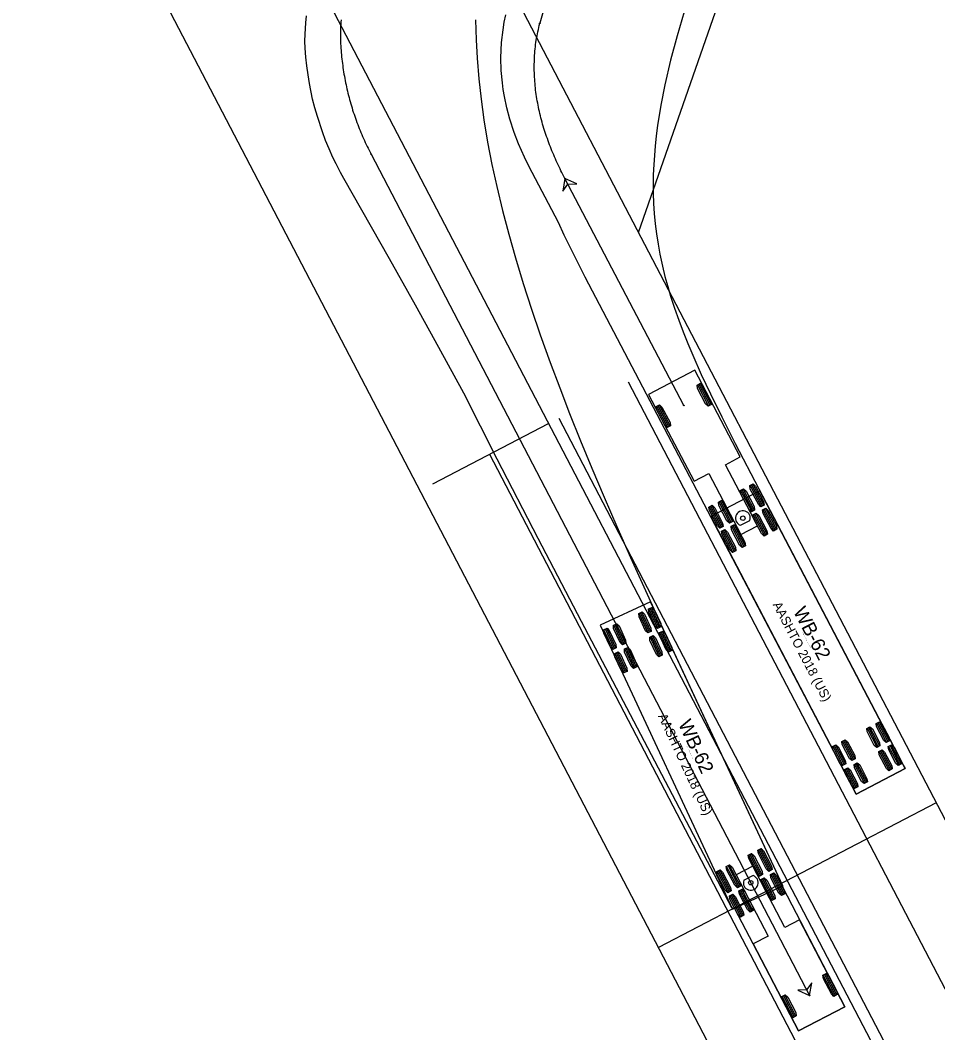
# Model space of a CAD drawing. Extents: x 2297881 to 2300600, y 559917 to 564426.
# Drawn here: x 2298929.2 to 2299069.8, y 562494.5 to 562649.6 of the extents above; entities that cross this region are included whole.
import ezdxf

# ---------------------------------------------------------------- set-up
doc = ezdxf.new("R2010")
doc.units = 0
for name, color, linetype in [('DR_X_Elev_Flow', 7, 'Continuous'), ('GE_X_Alignment', 7, 'Continuous'), ('PM_P_Channelizing_Line', 7, 'Continuous'), ('PM_P_Lane_Line', 7, 'Continuous'), ('SC_Scratch1', 7, 'Continuous'), ('SV_X_Control_Cells_Found', 7, 'Continuous'), ('UT_X_Telecom_Cells', 7, 'Continuous'), ('VG_X_Cells', 7, 'Continuous')]:
    doc.layers.add(name, color=color, linetype=linetype)

msp = doc.modelspace()

# ---------------------------------------------------------------- linework, layer by layer
at = {"layer": 'DR_X_Elev_Flow'}
for p, q in [((2299030.92, 562590.62), (2299012.69, 562625.4)), ((2299030.92, 562590.62), (2299012.69, 562625.4)), ((2299032.6, 562596.02), (2299025.52, 562592.3)), ((2299039.57, 562582.73), (2299032.6, 562596.02)), ((2299033.41, 562593.99), (2299035.11, 562590.74)), ((2299033, 562593.78), (2299034.7, 562590.53)), ((2299033.2, 562593.88), (2299034.91, 562590.64)), ((2299025.52, 562592.3), (2299032.48, 562579.02)), ((2299025.52, 562592.3), (2299025.52, 562592.3)), ((2299026.73, 562590.49), (2299028.43, 562587.24)), ((2299026.93, 562590.6), (2299028.63, 562587.35)), ((2299027.13, 562590.7), (2299028.83, 562587.45)), ((2299037.29, 562581.54), (2299039.57, 562582.73)), ((2299042.21, 562572.15), (2299037.29, 562581.54)), ((2299032.48, 562579.02), (2299034.75, 562580.21)), ((2299034.75, 562580.21), (2299039.67, 562570.82)), ((2299041.28, 562578.47), (2299042.98, 562575.22)), ((2299041.48, 562578.58), (2299043.18, 562575.33)), ((2299042.57, 562577.53), (2299035.04, 562573.59)), ((2299039.61, 562577.6), (2299041.32, 562574.35)), ((2299039.82, 562577.71), (2299041.52, 562574.46)), ((2299040.02, 562577.81), (2299041.72, 562574.56)), ((2299041.08, 562578.36), (2299042.78, 562575.12)), ((2299064.85, 562535.01), (2299042.57, 562577.53)), ((2299036.26, 562575.84), (2299037.97, 562572.6)), ((2299036.47, 562575.95), (2299038.17, 562572.7)), ((2299036.67, 562576.06), (2299038.37, 562572.81)), ((2299034.8, 562575.08), (2299036.5, 562571.83)), ((2299035.01, 562575.18), (2299036.71, 562571.94)), ((2299035.21, 562575.29), (2299036.91, 562572.04)), ((2299041.56, 562573.88), (2299043.27, 562570.63)), ((2299041.77, 562573.98), (2299043.47, 562570.74)), ((2299041.97, 562574.09), (2299043.67, 562570.84)), ((2299043.03, 562574.64), (2299044.73, 562571.4)), ((2299043.23, 562574.75), (2299044.93, 562571.5)), ((2299043.43, 562574.86), (2299045.13, 562571.61)), ((2299035.04, 562573.59), (2299057.32, 562531.07)), ((2299035.04, 562573.59), (2299035.04, 562573.59)), ((2299038.42, 562572.23), (2299040.12, 562568.98)), ((2299038.62, 562572.34), (2299040.32, 562569.09)), ((2299039.63, 562572.25), (2299041.06, 562573)), ((2299036.75, 562571.36), (2299038.45, 562568.11)), ((2299036.95, 562571.46), (2299038.66, 562568.22)), ((2299037.16, 562571.57), (2299038.86, 562568.32)), ((2299038.21, 562572.12), (2299039.91, 562568.87)), ((2299039.67, 562570.82), (2299042.21, 562572.15)), ((2299059.2, 562541.25), (2299060.73, 562538.33)), ((2299059.4, 562541.36), (2299060.93, 562538.44)), ((2299060.46, 562541.91), (2299061.99, 562538.99)), ((2299060.66, 562542.02), (2299062.19, 562539.1)), ((2299060.86, 562542.13), (2299062.39, 562539.2)), ((2299059, 562541.15), (2299060.53, 562538.22)), ((2299053.74, 562538.39), (2299055.27, 562535.47)), ((2299053.94, 562538.5), (2299055.47, 562535.58)), ((2299054.15, 562538.61), (2299055.68, 562535.68)), ((2299055.2, 562539.16), (2299056.73, 562536.24)), ((2299055.4, 562539.27), (2299056.94, 562536.34)), ((2299055.61, 562539.37), (2299057.14, 562536.45)), ((2299062.31, 562538.37), (2299063.85, 562535.45)), ((2299062.52, 562538.48), (2299064.05, 562535.55)), ((2299062.72, 562538.58), (2299064.25, 562535.66)), ((2299060.85, 562537.6), (2299062.38, 562534.68)), ((2299061.06, 562537.71), (2299062.59, 562534.79)), ((2299061.26, 562537.82), (2299062.79, 562534.89)), ((2299056, 562535.06), (2299057.53, 562532.14)), ((2299057.06, 562535.62), (2299058.59, 562532.69)), ((2299057.26, 562535.72), (2299058.79, 562532.8)), ((2299057.32, 562531.07), (2299064.85, 562535.01)), ((2299057.46, 562535.83), (2299059, 562532.91)), ((2299055.6, 562534.85), (2299057.13, 562531.93)), ((2299055.8, 562534.96), (2299057.33, 562532.03))]:
    msp.add_line(p, q, dxfattribs=at)
for points in [[(2299056.66, 562532.32), (2299015.81, 562610.29), (2299013.54, 562614.77), (2299012.6, 562616.71), (2299011.71, 562618.67), (2299007.18, 562627.3), (2299006.51, 562628.65), (2299005.59, 562630.7), (2299004.93, 562632.43), (2299004.25, 562634.5), (2299003.79, 562636.24), (2299003.42, 562637.98), (2299003.25, 562639.03), (2299003.11, 562640.08), (2299002.94, 562641.95), (2299002.89, 562643.9), (2299002.91, 562645.07), (2299002.98, 562646.24), (2299003.21, 562648.18), (2299003.4, 562649.34), (2299003.65, 562650.49)], [(2299030.96, 562650.95), (2299029.89, 562647.27), (2299028.9, 562643.54), (2299028.01, 562639.73), (2299027.4, 562636.62), (2299026.9, 562633.5), (2299026.69, 562631.94), (2299026.52, 562630.37), (2299026.31, 562627.54), (2299026.24, 562625.97), (2299026.22, 562624.72), (2299026.23, 562623.15), (2299026.29, 562621.58), (2299026.39, 562620.02), (2299026.54, 562618.46), (2299026.73, 562616.9), (2299026.97, 562615.34), (2299027.26, 562613.79), (2299027.66, 562611.94), (2299028.03, 562610.4), (2299028.45, 562608.87), (2299028.9, 562607.34), (2299029.49, 562605.52), (2299030.13, 562603.7), (2299030.81, 562601.89), (2299031.53, 562600.09), (2299032.28, 562598.3), (2299033.6, 562595.34), (2299034.99, 562592.39), (2299036.72, 562588.88), (2299038.79, 562584.8), (2299042.41, 562577.84), (2299064.25, 562536.16), (2299064.55, 562535.49), (2299064.85, 562535.01), (2299057.32, 562531.07), (2299056.66, 562532.32)], [(2299012.69, 562625.4), (2299012.54, 562625.7), (2299012.38, 562626), (2299012.23, 562626.29), (2299012.08, 562626.59), (2299011.94, 562626.89), (2299011.79, 562627.19), (2299011.65, 562627.49), (2299011.51, 562627.79), (2299011.37, 562628.1), (2299011.23, 562628.4), (2299011.1, 562628.71), (2299010.97, 562629.01), (2299010.84, 562629.32), (2299010.71, 562629.63), (2299010.58, 562629.94), (2299010.46, 562630.25), (2299010.34, 562630.56), (2299010.22, 562630.87), (2299010.11, 562631.18), (2299010, 562631.5), (2299009.89, 562631.81), (2299009.78, 562632.13), (2299009.67, 562632.44), (2299009.57, 562632.76), (2299009.47, 562633.08), (2299009.38, 562633.4), (2299009.28, 562633.72), (2299009.19, 562634.04), (2299009.11, 562634.36), (2299009.02, 562634.68), (2299008.94, 562635.01), (2299008.86, 562635.33), (2299008.79, 562635.65), (2299008.71, 562635.98), (2299008.65, 562636.31), (2299008.58, 562636.63), (2299008.52, 562636.96), (2299008.46, 562637.29), (2299008.4, 562637.62), (2299008.35, 562637.95), (2299008.3, 562638.28), (2299008.26, 562638.61), (2299008.21, 562638.94), (2299008.18, 562639.27), (2299008.14, 562639.6), (2299008.11, 562639.93), (2299008.08, 562640.26), (2299008.06, 562640.6), (2299008.04, 562640.93), (2299008.02, 562641.26), (2299008.01, 562641.59), (2299008, 562641.93), (2299008, 562642.26), (2299008, 562642.59), (2299008, 562642.93), (2299008.01, 562643.26), (2299008.02, 562643.59), (2299008.03, 562643.93), (2299008.05, 562644.26), (2299008.08, 562644.59), (2299008.1, 562644.92), (2299008.14, 562645.26), (2299008.17, 562645.59), (2299008.21, 562645.92), (2299008.26, 562646.25), (2299008.31, 562646.58), (2299008.36, 562646.91), (2299008.42, 562647.24), (2299008.48, 562647.56), (2299008.54, 562647.89), (2299008.62, 562648.22), (2299008.69, 562648.54), (2299008.77, 562648.86), (2299008.85, 562649.19)], [(2299012.69, 562625.4), (2299012.35, 562623.43), (2299013.16, 562624.52), (2299014.51, 562624.56), (2299012.69, 562625.4)], [(2299012.69, 562625.4), (2299012.35, 562623.43), (2299013.16, 562624.52), (2299014.51, 562624.56), (2299012.69, 562625.4)]]:
    msp.add_lwpolyline(points, dxfattribs=at)
for points in [[(2299012.69, 562625.4), (2299012.35, 562623.43), (2299013.16, 562624.52), (2299014.51, 562624.56)], [(2299012.69, 562625.4), (2299012.35, 562623.43), (2299013.16, 562624.52), (2299014.51, 562624.56)], [(2299032.95, 562593.75), (2299033.46, 562594.02), (2299033.85, 562593.64), (2299035.07, 562591.3), (2299035.16, 562590.77), (2299034.65, 562590.5), (2299034.26, 562590.88), (2299033.04, 562593.22)], [(2299026.68, 562590.46), (2299027.18, 562590.73), (2299027.57, 562590.35), (2299028.8, 562588.02), (2299028.88, 562587.48), (2299028.38, 562587.22), (2299027.99, 562587.59), (2299026.76, 562589.93)], [(2299041.03, 562578.34), (2299041.53, 562578.6), (2299041.92, 562578.23), (2299043.15, 562575.89), (2299043.23, 562575.36), (2299042.73, 562575.09), (2299042.34, 562575.47), (2299041.11, 562577.8)], [(2299039.56, 562577.57), (2299040.07, 562577.84), (2299040.46, 562577.46), (2299041.69, 562575.12), (2299041.77, 562574.59), (2299041.27, 562574.32), (2299040.88, 562574.7), (2299039.65, 562577.04)], [(2299034.75, 562575.05), (2299035.26, 562575.32), (2299035.65, 562574.94), (2299036.87, 562572.6), (2299036.96, 562572.07), (2299036.45, 562571.8), (2299036.06, 562572.18), (2299034.84, 562574.52)], [(2299036.21, 562575.82), (2299036.72, 562576.08), (2299037.11, 562575.71), (2299038.34, 562573.37), (2299038.42, 562572.83), (2299037.92, 562572.57), (2299037.52, 562572.94), (2299036.3, 562575.28)], [(2299041.51, 562573.85), (2299042.02, 562574.12), (2299042.41, 562573.74), (2299043.64, 562571.4), (2299043.72, 562570.87), (2299043.22, 562570.6), (2299042.82, 562570.98), (2299041.6, 562573.32)], [(2299042.98, 562574.62), (2299043.48, 562574.88), (2299043.87, 562574.51), (2299045.1, 562572.17), (2299045.18, 562571.64), (2299044.68, 562571.37), (2299044.29, 562571.74), (2299043.06, 562574.08)], [(2299038.16, 562572.1), (2299038.67, 562572.36), (2299039.06, 562571.99), (2299040.29, 562569.65), (2299040.37, 562569.11), (2299039.86, 562568.85), (2299039.47, 562569.22), (2299038.25, 562571.56)], [(2299036.7, 562571.33), (2299037.21, 562571.6), (2299037.6, 562571.22), (2299038.82, 562568.88), (2299038.91, 562568.35), (2299038.4, 562568.08), (2299038.01, 562568.46), (2299036.79, 562570.8)], [(2299058.95, 562541.12), (2299059.45, 562541.39), (2299059.82, 562541.06), (2299060.92, 562538.95), (2299060.98, 562538.46), (2299060.48, 562538.2), (2299060.11, 562538.53), (2299059.01, 562540.63)], [(2299060.41, 562541.89), (2299060.91, 562542.15), (2299061.28, 562541.82), (2299062.38, 562539.72), (2299062.45, 562539.23), (2299061.94, 562538.96), (2299061.57, 562539.29), (2299060.47, 562541.4)], [(2299053.69, 562538.37), (2299054.2, 562538.63), (2299054.56, 562538.3), (2299055.67, 562536.2), (2299055.73, 562535.71), (2299055.22, 562535.44), (2299054.85, 562535.77), (2299053.75, 562537.88)], [(2299055.15, 562539.13), (2299055.66, 562539.4), (2299056.02, 562539.07), (2299057.13, 562536.96), (2299057.19, 562536.47), (2299056.68, 562536.21), (2299056.32, 562536.54), (2299055.21, 562538.64)], [(2299062.26, 562538.34), (2299062.77, 562538.61), (2299063.14, 562538.28), (2299064.24, 562536.17), (2299064.3, 562535.69), (2299063.79, 562535.42), (2299063.43, 562535.75), (2299062.33, 562537.85)], [(2299060.8, 562537.58), (2299061.31, 562537.84), (2299061.68, 562537.51), (2299062.78, 562535.41), (2299062.84, 562534.92), (2299062.33, 562534.65), (2299061.97, 562534.98), (2299060.86, 562537.09)], [(2299055.55, 562534.82), (2299056.05, 562535.09), (2299056.42, 562534.76), (2299057.52, 562532.66), (2299057.58, 562532.17), (2299057.08, 562531.9), (2299056.71, 562532.23), (2299055.61, 562534.33)], [(2299057.01, 562535.59), (2299057.51, 562535.85), (2299057.88, 562535.53), (2299058.98, 562533.42), (2299059.05, 562532.93), (2299058.54, 562532.67), (2299058.17, 562533), (2299057.07, 562535.1)]]:
    msp.add_lwpolyline(points, close=True, dxfattribs=at)
for centre, radius in [((2299008.85, 562649.19), 0.0417), ((2299008.85, 562649.19), 0.0417), ((2299012.69, 562625.4), 0.0417), ((2299012.69, 562625.4), 0.0417), ((2299012.69, 562625.4), 0.0417), ((2299030.92, 562590.62), 0.0417), ((2299030.92, 562590.62), 0.0417), ((2299039.97, 562573.34), 0.34)]:
    msp.add_circle(centre, radius, dxfattribs=at)
for centre, radius, start, end in [((2299051.52, 562637.89), 44.14, 134.6492, 165.1685), ((2299039.97, 562573.34), 1.14, 342.6515, 252.6515)]:
    msp.add_arc(centre, radius, start, end, dxfattribs=at)
at = {"layer": 'GE_X_Alignment'}
msp.add_line((2298386.28, 563783.36), (2299396.64, 561847.4), dxfattribs=at)
at = {"layer": 'PM_P_Channelizing_Line'}
for p, q in [((2298982.98, 562629.13), (2299050.19, 562500.19)), ((2299025.82, 562560.52), (2299018.11, 562556.93)), ((2299046.09, 562517.01), (2299025.82, 562560.52)), ((2299025.45, 562555.77), (2299024.06, 562558.76)), ((2299025.66, 562555.87), (2299024.27, 562558.86)), ((2299025.87, 562555.97), (2299024.47, 562558.96)), ((2299026.95, 562556.47), (2299025.55, 562559.46)), ((2299027.16, 562556.57), (2299025.76, 562559.56)), ((2299027.36, 562556.66), (2299025.97, 562559.65)), ((2299018.11, 562556.93), (2299038.39, 562513.42)), ((2299021.57, 562553.96), (2299020.18, 562556.95)), ((2299021.78, 562554.06), (2299020.38, 562557.05)), ((2299021.98, 562554.16), (2299020.59, 562557.15)), ((2299020.07, 562553.27), (2299018.68, 562556.26)), ((2299020.28, 562553.36), (2299018.89, 562556.35)), ((2299020.49, 562553.46), (2299019.1, 562556.45)), ((2299027.14, 562552.15), (2299025.75, 562555.14)), ((2299027.35, 562552.24), (2299025.96, 562555.23)), ((2299027.56, 562552.34), (2299026.16, 562555.33)), ((2299028.64, 562552.84), (2299027.24, 562555.83)), ((2299028.84, 562552.94), (2299027.45, 562555.93)), ((2299029.05, 562553.04), (2299027.66, 562556.03)), ((2299021.76, 562549.64), (2299020.37, 562552.63)), ((2299021.97, 562549.74), (2299020.58, 562552.73)), ((2299022.18, 562549.83), (2299020.78, 562552.83)), ((2299023.26, 562550.34), (2299021.86, 562553.33)), ((2299023.47, 562550.43), (2299022.07, 562553.43)), ((2299023.67, 562550.53), (2299022.28, 562553.52)), ((2299044.2, 562519.36), (2299042.51, 562522.61)), ((2299044.4, 562519.46), (2299042.71, 562522.71)), ((2299042.53, 562518.49), (2299040.84, 562521.74)), ((2299042.74, 562518.59), (2299041.04, 562521.85)), ((2299042.94, 562518.7), (2299041.25, 562521.95)), ((2299044, 562519.25), (2299042.3, 562522.5)), ((2299039.18, 562516.74), (2299037.48, 562519.99)), ((2299039.38, 562516.85), (2299037.69, 562520.1)), ((2299039.58, 562516.95), (2299037.89, 562520.2)), ((2299041.48, 562520.01), (2299038.94, 562518.68)), ((2299046.38, 562510.61), (2299041.48, 562520.01)), ((2299037.71, 562515.98), (2299036.02, 562519.23)), ((2299037.92, 562516.08), (2299036.22, 562519.34)), ((2299038.12, 562516.19), (2299036.43, 562519.44)), ((2299038.94, 562518.68), (2299043.84, 562509.28)), ((2299041.53, 562518.57), (2299040.09, 562517.83)), ((2299044.47, 562514.76), (2299042.78, 562518.01)), ((2299044.68, 562514.87), (2299042.98, 562518.12)), ((2299044.88, 562514.97), (2299043.19, 562518.23)), ((2299045.94, 562515.52), (2299044.24, 562518.78)), ((2299046.14, 562515.63), (2299044.45, 562518.88)), ((2299046.34, 562515.74), (2299044.65, 562518.99)), ((2299038.39, 562513.42), (2299046.09, 562517.01)), ((2299041.32, 562513.12), (2299039.63, 562516.37)), ((2299041.52, 562513.23), (2299039.83, 562516.48)), ((2299046.09, 562517.01), (2299046.09, 562517.01)), ((2299039.65, 562512.25), (2299037.96, 562515.5)), ((2299039.86, 562512.36), (2299038.16, 562515.61)), ((2299040.06, 562512.46), (2299038.37, 562515.72)), ((2299041.12, 562513.01), (2299039.42, 562516.27)), ((2299048.66, 562511.79), (2299046.38, 562510.61)), ((2299055.59, 562498.49), (2299048.66, 562511.79)), ((2299043.84, 562509.28), (2299041.56, 562508.1)), ((2299041.56, 562508.1), (2299048.49, 562494.79)), ((2299053.97, 562500.09), (2299052.28, 562503.34)), ((2299054.18, 562500.2), (2299052.48, 562503.45)), ((2299054.38, 562500.3), (2299052.69, 562503.56)), ((2299047.69, 562496.82), (2299046, 562500.07)), ((2299047.9, 562496.93), (2299046.2, 562500.18)), ((2299048.1, 562497.03), (2299046.4, 562500.28)), ((2299048.49, 562494.79), (2299055.59, 562498.49)), ((2299055.59, 562498.49), (2299055.59, 562498.49))]:
    msp.add_line(p, q, dxfattribs=at)
for points in [[(2298999.01, 562649.7), (2298999.08, 562646.64), (2298999.22, 562643.84), (2298999.49, 562640.68), (2298999.84, 562637.53), (2299000.28, 562634.39), (2299000.85, 562630.96), (2299001.51, 562627.56), (2299002.24, 562624.18), (2299003.12, 562620.51), (2299004.08, 562616.86), (2299005.12, 562613.22), (2299006.31, 562609.28), (2299007.58, 562605.35), (2299008.92, 562601.43), (2299010.43, 562597.22), (2299011.89, 562593.31), (2299013.4, 562589.41), (2299015.07, 562585.21), (2299016.8, 562581.02), (2299018.7, 562576.54), (2299020.64, 562572.07), (2299022.75, 562567.3), (2299025.04, 562562.25), (2299027.36, 562557.2), (2299046.06, 562517.08), (2299046.08, 562516.73), (2299055.59, 562498.49), (2299048.49, 562494.79), (2299041.55, 562508.11), (2299038.74, 562513.5), (2299038.26, 562513.66), (2299015.24, 562557.52), (2299008.6, 562570.22), (2299002.31, 562582.38), (2298997.21, 562592.48), (2298993.38, 562599.52), (2298989.8, 562605.98), (2298985.8, 562613.1), (2298978.8, 562625.38), (2298978.28, 562626.34), (2298977.61, 562627.64), (2298977.14, 562628.61), (2298976.56, 562629.92), (2298976.02, 562631.23), (2298975.52, 562632.55), (2298974.75, 562634.88), (2298974.37, 562636.22), (2298974.03, 562637.57), (2298973.54, 562639.93), (2298973.32, 562641.29), (2298973.13, 562642.65), (2298972.99, 562644.01), (2298972.88, 562645.39), (2298972.85, 562646.45), (2298972.86, 562647.51), (2298972.97, 562649.26), (2298973.08, 562650.31)], [(2298978.39, 562649.69), (2298978.36, 562649.36), (2298978.33, 562649.03), (2298978.31, 562648.7), (2298978.3, 562648.36), (2298978.29, 562648.03), (2298978.28, 562647.7), (2298978.28, 562647.36), (2298978.28, 562647.03), (2298978.29, 562646.7), (2298978.3, 562646.36), (2298978.32, 562646.03), (2298978.34, 562645.7), (2298978.36, 562645.36), (2298978.38, 562645.03), (2298978.41, 562644.7), (2298978.44, 562644.37), (2298978.47, 562644.04), (2298978.51, 562643.7), (2298978.55, 562643.37), (2298978.59, 562643.04), (2298978.63, 562642.71), (2298978.68, 562642.38), (2298978.73, 562642.05), (2298978.78, 562641.72), (2298978.83, 562641.39), (2298978.89, 562641.07), (2298978.95, 562640.74), (2298979.01, 562640.41), (2298979.08, 562640.08), (2298979.14, 562639.76), (2298979.21, 562639.43), (2298979.29, 562639.11), (2298979.36, 562638.78), (2298979.44, 562638.46), (2298979.52, 562638.13), (2298979.61, 562637.81), (2298979.69, 562637.49), (2298979.78, 562637.17), (2298979.87, 562636.85), (2298979.96, 562636.53), (2298980.06, 562636.21), (2298980.16, 562635.89), (2298980.26, 562635.57), (2298980.37, 562635.26), (2298980.47, 562634.94), (2298980.58, 562634.63), (2298980.69, 562634.31), (2298980.81, 562634), (2298980.93, 562633.69), (2298981.04, 562633.37), (2298981.17, 562633.06), (2298981.29, 562632.76), (2298981.42, 562632.45), (2298981.55, 562632.14), (2298981.68, 562631.83), (2298981.81, 562631.53), (2298981.95, 562631.23), (2298982.09, 562630.92), (2298982.23, 562630.62), (2298982.38, 562630.32), (2298982.52, 562630.02), (2298982.67, 562629.72), (2298982.82, 562629.43), (2298982.98, 562629.13)], [(2299050.19, 562500.19), (2299050.54, 562502.16), (2299049.73, 562501.08), (2299048.38, 562501.03), (2299050.19, 562500.19)]]:
    msp.add_lwpolyline(points, dxfattribs=at)
for points in [[(2299025.92, 562555.99), (2299025.4, 562555.75), (2299025.05, 562556.09), (2299024.05, 562558.25), (2299024.01, 562558.74), (2299024.53, 562558.98), (2299024.88, 562558.63), (2299025.88, 562556.48)], [(2299027.41, 562556.69), (2299026.9, 562556.44), (2299026.54, 562556.79), (2299025.54, 562558.94), (2299025.5, 562559.44), (2299026.02, 562559.68), (2299026.37, 562559.33), (2299027.38, 562557.18)], [(2299022.04, 562554.18), (2299021.52, 562553.94), (2299021.17, 562554.29), (2299020.16, 562556.44), (2299020.12, 562556.93), (2299020.64, 562557.17), (2299020.99, 562556.83), (2299022, 562554.67)], [(2299020.54, 562553.48), (2299020.02, 562553.24), (2299019.67, 562553.59), (2299018.67, 562555.74), (2299018.63, 562556.23), (2299019.15, 562556.48), (2299019.5, 562556.13), (2299020.5, 562553.98)], [(2299027.61, 562552.36), (2299027.09, 562552.12), (2299026.74, 562552.47), (2299025.73, 562554.62), (2299025.7, 562555.11), (2299026.21, 562555.36), (2299026.57, 562555.01), (2299027.57, 562552.86)], [(2299029.1, 562553.06), (2299028.59, 562552.82), (2299028.23, 562553.17), (2299027.23, 562555.32), (2299027.19, 562555.81), (2299027.71, 562556.05), (2299028.06, 562555.71), (2299029.06, 562553.55)], [(2299022.23, 562549.86), (2299021.71, 562549.62), (2299021.36, 562549.96), (2299020.36, 562552.12), (2299020.32, 562552.61), (2299020.84, 562552.85), (2299021.19, 562552.5), (2299022.19, 562550.35)], [(2299023.73, 562550.55), (2299023.21, 562550.31), (2299022.86, 562550.66), (2299021.85, 562552.81), (2299021.81, 562553.3), (2299022.33, 562553.55), (2299022.68, 562553.2), (2299023.69, 562551.05)], [(2299044.45, 562519.49), (2299043.95, 562519.22), (2299043.56, 562519.6), (2299042.34, 562521.94), (2299042.25, 562522.48), (2299042.76, 562522.74), (2299043.15, 562522.36), (2299044.37, 562520.02)], [(2299042.99, 562518.73), (2299042.48, 562518.46), (2299042.09, 562518.84), (2299040.87, 562521.18), (2299040.79, 562521.71), (2299041.3, 562521.98), (2299041.69, 562521.6), (2299042.91, 562519.26)], [(2299038.17, 562516.22), (2299037.66, 562515.95), (2299037.27, 562516.33), (2299036.05, 562518.67), (2299035.97, 562519.2), (2299036.48, 562519.47), (2299036.87, 562519.09), (2299038.09, 562516.75)], [(2299039.63, 562516.98), (2299039.13, 562516.71), (2299038.74, 562517.09), (2299037.52, 562519.43), (2299037.43, 562519.97), (2299037.94, 562520.23), (2299038.33, 562519.85), (2299039.55, 562517.51)], [(2299044.93, 562515), (2299044.42, 562514.74), (2299044.03, 562515.11), (2299042.81, 562517.45), (2299042.73, 562517.99), (2299043.24, 562518.25), (2299043.63, 562517.88), (2299044.85, 562515.54)], [(2299046.39, 562515.76), (2299045.89, 562515.5), (2299045.5, 562515.87), (2299044.28, 562518.22), (2299044.19, 562518.75), (2299044.7, 562519.01), (2299045.09, 562518.64), (2299046.31, 562516.3)], [(2299041.57, 562513.25), (2299041.07, 562512.99), (2299040.68, 562513.36), (2299039.46, 562515.71), (2299039.37, 562516.24), (2299039.88, 562516.5), (2299040.27, 562516.13), (2299041.49, 562513.79)], [(2299040.11, 562512.49), (2299039.6, 562512.23), (2299039.21, 562512.6), (2299037.99, 562514.94), (2299037.91, 562515.48), (2299038.42, 562515.74), (2299038.81, 562515.37), (2299040.03, 562513.03)], [(2299054.43, 562500.33), (2299053.92, 562500.07), (2299053.53, 562500.44), (2299052.31, 562502.78), (2299052.23, 562503.32), (2299052.74, 562503.58), (2299053.13, 562503.21), (2299054.35, 562500.87)], [(2299050.19, 562500.19), (2299050.54, 562502.16), (2299049.73, 562501.08), (2299048.38, 562501.03)], [(2299048.15, 562497.06), (2299047.64, 562496.79), (2299047.25, 562497.17), (2299046.03, 562499.51), (2299045.95, 562500.05), (2299046.45, 562500.31), (2299046.84, 562499.93), (2299048.07, 562497.59)]]:
    msp.add_lwpolyline(points, close=True, dxfattribs=at)
for centre, radius in [((2298982.98, 562629.13), 0.0417), ((2299041.18, 562517.48), 0.34), ((2299050.19, 562500.19), 0.0417)]:
    msp.add_circle(centre, radius, dxfattribs=at)
msp.add_arc((2299041.18, 562517.48), 1.14, 162.5126, 72.5126, dxfattribs=at)
at = {"layer": 'PM_P_Lane_Line'}
for p, q in [((2298467.65, 563579.35), (2299376.95, 561837.04)), ((2298843.32, 562963.26), (2299419.43, 561859.39))]:
    msp.add_line(p, q, dxfattribs=at)
at = {"layer": 'SC_Scratch1'}
for p, q in [((2299023.98, 562617.11), (2299048.95, 562688.7)), ((2298992.46, 562578.62), (2299010.19, 562587.87)), ((2299069.57, 562529.75), (2299027.02, 562507.54))]:
    msp.add_line(p, q, dxfattribs=at)
at = {"layer": 'SV_X_Control_Cells_Found'}
msp.add_line((2299001.11, 562583.13), (2299365.23, 561885.43), dxfattribs=at)
at = {"layer": 'UT_X_Telecom_Cells'}
msp.add_line((2299022.38, 562594.23), (2299226.89, 562202.39), dxfattribs=at)
at = {"layer": 'VG_X_Cells'}
msp.add_line((2299011.74, 562588.68), (2299216.25, 562196.84), dxfattribs=at)

# ---------------------------------------------------------------- texts
at = {"layer": 'DR_X_Elev_Flow'}
for s, height, p in [('AASHTO 2018 (US)', 1.4167, (2299044.5, 562560.1)), ('WB-62', 2.125, (2299047.63, 562559.08)), ('(c) 2021 Transoft Solutions, Inc. All rights reserved.', 0.085, (2299049.1, 562555.81))]:
    msp.add_text(s, height=height, rotation=297.6515, dxfattribs=at).set_placement(p)
at = {"layer": 'PM_P_Channelizing_Line'}
for s, height, p in [('AASHTO 2018 (US)', 1.4167, (2299026.93, 562543.02)), ('WB-62', 2.125, (2299030.01, 562541.86)), ('(c) 2021 Transoft Solutions, Inc. All rights reserved.', 0.085, (2299031.33, 562538.52))]:
    msp.add_text(s, height=height, rotation=294.9818, dxfattribs=at).set_placement(p)

doc.saveas('drawing.dxf')
